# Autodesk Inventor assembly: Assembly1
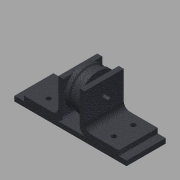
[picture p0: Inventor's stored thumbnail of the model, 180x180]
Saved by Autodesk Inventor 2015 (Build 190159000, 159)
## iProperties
Created: 2014-07
Part Number: Assembly1
Document SubType Name: Assembly
Designer: CADCIM
Author: CADCIM
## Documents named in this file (5)
- C:\Users\CADCIM\Desktop\c19_Inventor2014_tut\Tutorial 3\Assembly1.iam
- C:\Users\CADCIM\Desktop\c19_Inventor2014_tut\Tutorial 3\Base.ipt
- C:\Users\CADCIM\Desktop\c19_Inventor2014_tut\Tutorial 3\Support.ipt
- C:\Users\CADCIM\Desktop\c19_Inventor2014_tut\Tutorial 3\Whell.ipt
- C:\Users\CADCIM\Desktop\c19_Inventor2014_tut\Tutorial 3\Shoulder screw.ipt
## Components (5 placed, 4 different names)
1. Base:2 — Insert:1, Insert:2, Mate:2, Mate:3
2. Support:1 — Insert:1, Mate:3, Mate:4, Mate:5, Mate:6
3. Support:2 — Insert:2, Mate:1, Mate:2
4. Whell:1 — Mate:1, Mate:4
5. Shoulder screw:1 — Mate:5, Mate:6
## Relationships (8: Mate 6, Insert 2)
- Insert:1: Base:2 ↔ Support:1
- Insert:2: Base:2 ↔ Support:2
- Mate:1: Support:2 ↔ Whell:1
- Mate:2: Base:2 ↔ Support:2
- Mate:3: Base:2 ↔ Support:1
- Mate:4: Support:1 ↔ Whell:1
- Mate:5: Support:1 ↔ Shoulder screw:1
- Mate:6: Support:1 ↔ Shoulder screw:1
